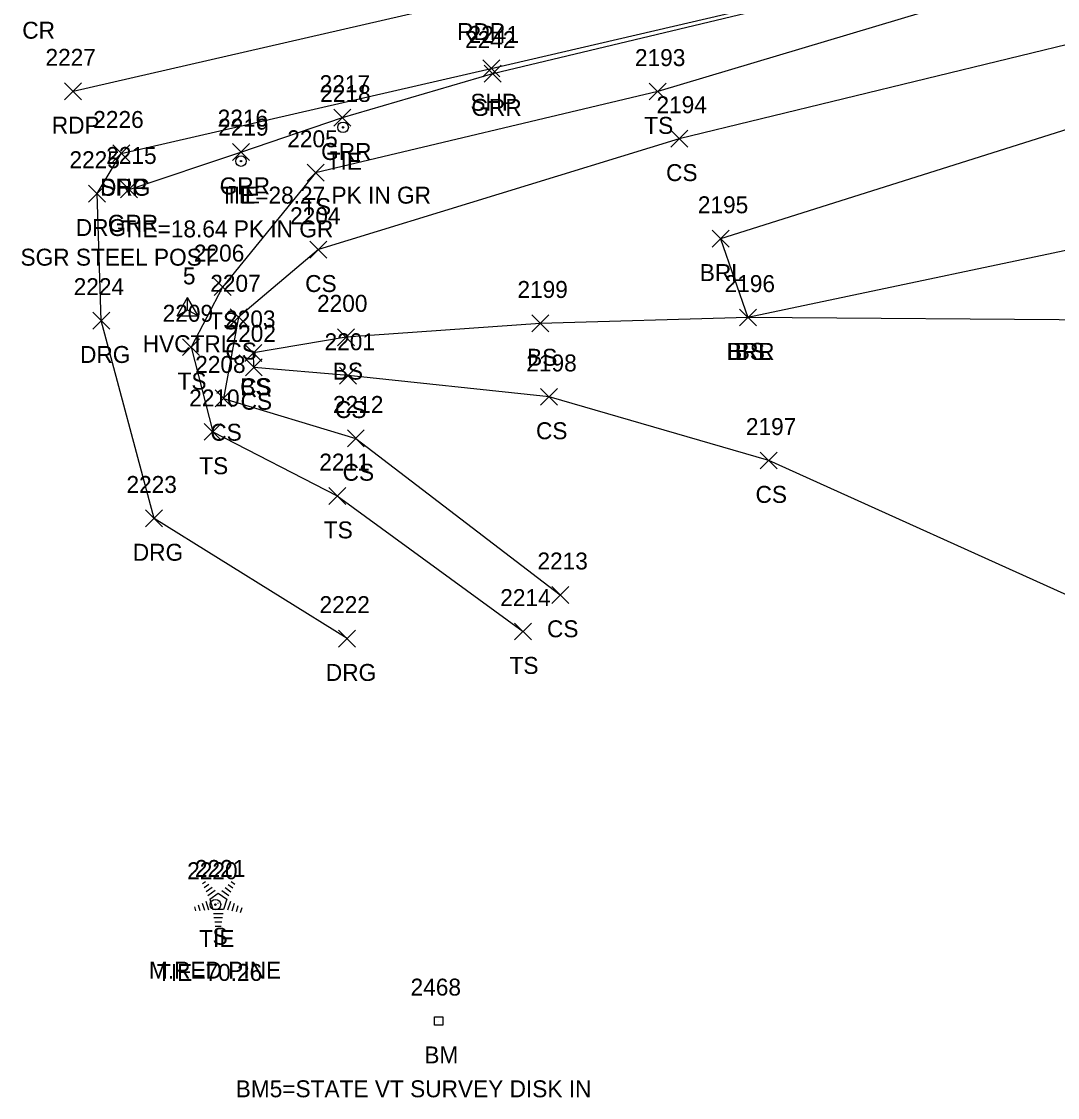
# Model space of a CAD drawing. Extents: x 1502194 to 1507887, y 142265 to 144150.
# Drawn here: x 1506530.8 to 1506653.1, y 143322.6 to 143449.6 of the extents above; entities that cross this region are included whole.
import ezdxf

# ---------------------------------------------------------------- set-up
doc = ezdxf.new("R2010")
doc.units = 0
for name, color, linetype in [('C_A', 7, 'Continuous'), ('C_C', 7, 'Continuous'), ('C_I', 7, 'Continuous'), ('CBP', 7, 'Continuous'), ('CPBM', 7, 'Continuous'), ('CPSM', 7, 'Continuous'), ('L_A', 7, 'Continuous'), ('L_C', 7, 'Continuous'), ('L_I', 7, 'Continuous'), ('L_TIC', 7, 'Continuous'), ('LABL', 7, 'Continuous'), ('LELB', 7, 'Continuous'), ('LTC', 7, 'Continuous'), ('P_A', 7, 'Continuous'), ('P_I', 7, 'Continuous'), ('P_TIC', 7, 'Continuous'), ('PET', 7, 'Continuous'), ('PSP', 7, 'Continuous'), ('R_A', 7, 'Continuous'), ('R_C', 7, 'Continuous'), ('R_I', 7, 'Continuous'), ('R_TIC', 7, 'Continuous'), ('RDG', 7, 'Continuous'), ('RGR', 7, 'Continuous')]:
    doc.layers.add(name, color=color, linetype=linetype)

msp = doc.modelspace()

# ---------------------------------------------------------------- linework, layer by layer
at = {"layer": 'CBP'}
for centre, radius in [((1506568.74, 143437.08), 0.625), ((1506568.74, 143437.08), 0.0833), ((1506556.7, 143433.1), 0.625), ((1506556.7, 143433.1), 0.0833), ((1506553.68, 143345.36), 0.625), ((1506553.68, 143345.36), 0.0833)]:
    msp.add_circle(centre, radius, dxfattribs=at)
at = {"layer": 'CPBM'}
for p, q in [((1506579.52, 143331.13), (1506579.52, 143332.13)), ((1506579.52, 143332.13), (1506580.52, 143332.13)), ((1506580.52, 143332.13), (1506580.52, 143331.13)), ((1506580.52, 143331.13), (1506579.52, 143331.13)), ((1506580.02, 143331.63), (1506580.02, 143331.63)), ((1506580.02, 143331.63), (1506580.02, 143331.63))]:
    msp.add_line(p, q, dxfattribs=at)
at = {"layer": 'CPSM'}
for p, q in [((1506549.15, 143414.83), (1506550.4, 143417)), ((1506551.65, 143414.83), (1506550.4, 143417)), ((1506550.4, 143415.55), (1506550.4, 143417)), ((1506549.15, 143414.83), (1506550.4, 143415.55)), ((1506549.15, 143414.83), (1506551.65, 143414.83)), ((1506550.4, 143415.55), (1506550.4, 143415.55)), ((1506550.4, 143415.55), (1506551.65, 143414.83))]:
    msp.add_line(p, q, dxfattribs=at)
at = {"layer": 'L_TIC'}
for points in [[(1506604.88, 143440.31), (1506606.88, 143442.31)], [(1506606.88, 143440.31), (1506604.88, 143442.31)], [(1506607.42, 143434.74), (1506609.42, 143436.74)], [(1506609.42, 143434.74), (1506607.42, 143436.74)], [(1506564.5, 143430.73), (1506566.5, 143432.73)], [(1506566.5, 143430.73), (1506564.5, 143432.73)], [(1506612.3, 143422.94), (1506614.3, 143424.94)], [(1506614.3, 143422.94), (1506612.3, 143424.94)], [(1506564.83, 143421.65), (1506566.83, 143423.65)], [(1506566.83, 143421.65), (1506564.83, 143423.65)], [(1506553.53, 143417.24), (1506555.53, 143419.24)], [(1506555.53, 143417.24), (1506553.53, 143419.24)], [(1506555.41, 143413.68), (1506557.41, 143415.68)], [(1506557.41, 143413.68), (1506555.41, 143415.68)], [(1506615.52, 143413.64), (1506617.52, 143415.64)], [(1506617.52, 143413.64), (1506615.52, 143415.64)], [(1506615.52, 143413.64), (1506617.52, 143415.64)], [(1506617.52, 143413.64), (1506615.52, 143415.64)], [(1506615.52, 143413.64), (1506617.52, 143415.64)], [(1506617.52, 143413.64), (1506615.52, 143415.64)], [(1506591.02, 143412.95), (1506593.02, 143414.95)], [(1506593.02, 143412.95), (1506591.02, 143414.95)], [(1506568.09, 143411.31), (1506570.09, 143413.31)], [(1506570.09, 143411.31), (1506568.09, 143413.31)], [(1506549.8, 143410.14), (1506551.8, 143412.14)], [(1506551.8, 143410.14), (1506549.8, 143412.14)], [(1506557.16, 143409.47), (1506559.16, 143411.47)], [(1506559.16, 143409.47), (1506557.16, 143411.47)], [(1506557.16, 143409.47), (1506559.16, 143411.47)], [(1506559.16, 143409.47), (1506557.16, 143411.47)], [(1506557.21, 143407.76), (1506559.21, 143409.76)], [(1506559.21, 143407.76), (1506557.21, 143409.76)], [(1506568.34, 143406.78), (1506570.34, 143408.78)], [(1506570.34, 143406.78), (1506568.34, 143408.78)], [(1506553.63, 143404.1), (1506555.63, 143406.1)], [(1506555.63, 143404.1), (1506553.63, 143406.1)], [(1506592.06, 143404.28), (1506594.06, 143406.28)], [(1506594.06, 143404.28), (1506592.06, 143406.28)], [(1506552.36, 143400.15), (1506554.36, 143402.15)], [(1506554.36, 143400.15), (1506552.36, 143402.15)], [(1506569.25, 143399.38), (1506571.25, 143401.38)], [(1506571.25, 143399.38), (1506569.25, 143401.38)], [(1506617.98, 143396.77), (1506619.98, 143398.77)], [(1506619.98, 143396.77), (1506617.98, 143398.77)], [(1506567.06, 143392.58), (1506569.06, 143394.58)], [(1506569.06, 143392.58), (1506567.06, 143394.58)], [(1506593.37, 143380.91), (1506595.37, 143382.91)], [(1506595.37, 143380.91), (1506593.37, 143382.91)], [(1506588.98, 143376.59), (1506590.98, 143378.59)], [(1506590.98, 143376.59), (1506588.98, 143378.59)]]:
    msp.add_lwpolyline(points, dxfattribs=at)
at = {"layer": 'LABL'}
for points in [[(1506925.15, 143533.52), (1506885.27, 143516.72), (1506839.01, 143491.82), (1506812.47, 143480.11), (1506797.79, 143478.92), (1506756.88, 143465.31), (1506714.98, 143450.06), (1506660.24, 143438.77), (1506613.3, 143423.94), (1506616.52, 143414.64)], [(1506850.82, 143464.05), (1506827.75, 143457.15), (1506806.24, 143448.63), (1506776.99, 143440.27), (1506769, 143436.63), (1506724.43, 143433.85), (1506664.3, 143424.7), (1506616.52, 143414.64)]]:
    msp.add_lwpolyline(points, dxfattribs=at)
at = {"layer": 'LELB'}
for points in [[(1506920.49, 143550.15), (1506879.81, 143532.73), (1506832.93, 143512.84), (1506791.89, 143498.35), (1506750.34, 143484.06), (1506703.75, 143467.85), (1506654.25, 143455.79), (1506605.88, 143441.31), (1506565.5, 143431.73), (1506554.53, 143418.24), (1506550.8, 143411.14), (1506553.36, 143401.15), (1506568.06, 143393.58), (1506589.98, 143377.59)], [(1506885.27, 143516.72), (1506836.36, 143503.21), (1506808.72, 143492.99), (1506794.07, 143487.49), (1506753.53, 143475.43), (1506709.32, 143458.78), (1506657.01, 143447.54), (1506608.42, 143435.74), (1506565.83, 143422.65), (1506556.41, 143414.68), (1506554.63, 143405.1), (1506570.25, 143400.38), (1506594.37, 143381.91)], [(1506682.41, 143418.03), (1506666.9, 143416.56), (1506658.47, 143414.34), (1506616.52, 143414.64), (1506592.02, 143413.95), (1506569.09, 143412.31), (1506558.16, 143410.47)], [(1506821.73, 143363.41), (1506805.08, 143357), (1506771.29, 143358.16), (1506752.16, 143369.48), (1506733.38, 143373.29), (1506711.32, 143372.85), (1506683.88, 143374.9), (1506657.49, 143380.4), (1506618.98, 143397.77), (1506593.06, 143405.28), (1506569.34, 143407.78), (1506558.21, 143408.76), (1506558.16, 143410.47)]]:
    msp.add_lwpolyline(points, dxfattribs=at)
at = {"layer": 'LTC'}
for p, q in [((1506552.15, 143347.84), (1506552.51, 143348.1)), ((1506552.36, 143347.37), (1506552.89, 143347.76)), ((1506552.57, 143346.91), (1506553.28, 143347.42)), ((1506552.78, 143346.44), (1506553.66, 143347.08)), ((1506554.44, 143347.03), (1506555.25, 143346.45)), ((1506554.81, 143347.38), (1506555.49, 143346.89)), ((1506555.18, 143347.73), (1506555.73, 143347.33)), ((1506555.55, 143348.08), (1506555.97, 143347.77)), ((1506552.55, 143345.77), (1506552.88, 143344.75)), ((1506553.01, 143345.99), (1506554.02, 143346.72)), ((1506553.01, 143345.99), (1506553.39, 143344.79)), ((1506554.02, 143346.72), (1506555.02, 143346)), ((1506555.02, 143346), (1506554.62, 143344.79)), ((1506551.19, 143345.12), (1506551.34, 143344.65)), ((1506551.64, 143345.33), (1506551.85, 143344.68)), ((1506552.1, 143345.55), (1506552.37, 143344.72)), ((1506554.62, 143344.79), (1506553.39, 143344.79)), ((1506555.45, 143345.73), (1506555.12, 143344.69)), ((1506555.9, 143345.48), (1506555.61, 143344.59)), ((1506556.34, 143345.23), (1506556.11, 143344.5)), ((1506556.79, 143344.97), (1506556.6, 143344.4)), ((1506554.59, 143344.29), (1506553.44, 143344.29)), ((1506554.5, 143343.79), (1506553.51, 143343.79)), ((1506554.42, 143343.29), (1506553.59, 143343.29)), ((1506554.34, 143342.79), (1506553.66, 143342.79))]:
    msp.add_line(p, q, dxfattribs=at)
at = {"layer": 'P_TIC'}
for points in [[(1506585.24, 143443.04), (1506587.24, 143445.04)], [(1506587.24, 143443.04), (1506585.24, 143445.04)], [(1506535.88, 143440.34), (1506537.88, 143442.34)], [(1506537.88, 143440.34), (1506535.88, 143442.34)], [(1506541.57, 143433.01), (1506543.57, 143435.01)], [(1506543.57, 143433.01), (1506541.57, 143435.01)]]:
    msp.add_lwpolyline(points, dxfattribs=at)
at = {"layer": 'PET'}
msp.add_lwpolyline([(1506536.88, 143441.34), (1506584.71, 143452.38), (1506632.33, 143463.25), (1506682.2, 143476.4), (1506730.21, 143490.72), (1506780.44, 143507.94), (1506828.66, 143525.9), (1506867.29, 143541.82), (1506915.31, 143562.43)], dxfattribs=at)
at = {"layer": 'PSP'}
msp.add_lwpolyline([(1506542.57, 143434.01), (1506586.24, 143444.04), (1506633.16, 143454.96), (1506684.08, 143468.88), (1506730.5, 143482.95), (1506782.84, 143500.58), (1506831.22, 143518.57), (1506871.13, 143534.59), (1506917.52, 143554.61)], dxfattribs=at)
at = {"layer": 'R_TIC'}
for points in [[(1506585.4, 143442.43), (1506587.4, 143444.43)], [(1506587.4, 143442.43), (1506585.4, 143444.43)], [(1506567.66, 143437.23), (1506569.66, 143439.23)], [(1506569.66, 143437.23), (1506567.66, 143439.23)], [(1506541.57, 143433.01), (1506543.57, 143435.01)], [(1506543.57, 143433.01), (1506541.57, 143435.01)], [(1506555.69, 143433.17), (1506557.69, 143435.17)], [(1506557.69, 143433.17), (1506555.69, 143435.17)], [(1506538.71, 143428.26), (1506540.71, 143430.26)], [(1506540.71, 143428.26), (1506538.71, 143430.26)], [(1506542.48, 143428.76), (1506544.48, 143430.76)], [(1506544.48, 143428.76), (1506542.48, 143430.76)], [(1506539.21, 143413.28), (1506541.21, 143415.28)], [(1506541.21, 143413.28), (1506539.21, 143415.28)], [(1506545.44, 143389.94), (1506547.44, 143391.94)], [(1506547.44, 143389.94), (1506545.44, 143391.94)], [(1506568.22, 143375.76), (1506570.22, 143377.76)], [(1506570.22, 143375.76), (1506568.22, 143377.76)]]:
    msp.add_lwpolyline(points, dxfattribs=at)
at = {"layer": 'RDG'}
msp.add_lwpolyline([(1506569.22, 143376.76), (1506546.44, 143390.94), (1506540.21, 143414.28), (1506539.71, 143429.26), (1506542.57, 143434.01)], dxfattribs=at)
at = {"layer": 'RGR'}
msp.add_lwpolyline([(1506543.48, 143429.76), (1506556.69, 143434.17), (1506568.66, 143438.23), (1506586.4, 143443.43), (1506633.04, 143454.6), (1506684.23, 143468.58), (1506730.71, 143482.6), (1506783.02, 143500.15), (1506831.56, 143518.03), (1506871.47, 143534.19), (1506917.7, 143554.27)], dxfattribs=at)

# ---------------------------------------------------------------- texts
at = {"layer": 'C_A'}
for s, p in [('TIE', (1506566.82, 143432.08)), ('TIE', (1506554.78, 143428.1)), ('HVCTRL', (1506545.1, 143410.55)), ('TIE', (1506551.76, 143340.36)), ('BM', (1506578.33, 143326.63))]:
    msp.add_text(s, height=2, dxfattribs=at).set_placement(p)
at = {"layer": 'C_C'}
for s, p in [('TIE=28.27 PK IN GR', (1506554.22, 143428.08)), ('TIE=18.64 PK IN GR', (1506542.69, 143424.1)), ('TIE=70.26', (1506546.78, 143336.36)), ('BM5=STATE VT SURVEY DISK IN', (1506556.07, 143322.63))]:
    msp.add_text(s, height=2, dxfattribs=at).set_placement(p)
at = {"layer": 'C_I'}
for s, p in [('2218', (1506566.05, 143440.08)), ('2219', (1506554, 143436.1)), ('5', (1506549.84, 143418.55)), ('2220', (1506550.34, 143348.36)), ('2468', (1506576.71, 143334.63))]:
    msp.add_text(s, height=2, dxfattribs=at).set_placement(p)
at = {"layer": 'L_A'}
for s, p in [('TS', (1506604.29, 143436.31)), ('CS', (1506606.86, 143430.74)), ('TS', (1506563.91, 143426.73)), ('BRL', (1506610.84, 143418.94)), ('CS', (1506564.27, 143417.65)), ('TS', (1506552.94, 143413.24)), ('CS', (1506554.85, 143409.68)), ('BS', (1506590.46, 143408.95)), ('BRR', (1506614.01, 143409.64)), ('BRL', (1506614.06, 143409.64)), ('BS', (1506614.96, 143409.64)), ('BS', (1506567.53, 143407.31)), ('TS', (1506549.21, 143406.14)), ('CS', (1506556.6, 143405.47)), ('BS', (1506556.6, 143405.47)), ('CS', (1506556.65, 143403.76)), ('CS', (1506567.78, 143402.78)), ('CS', (1506553.07, 143400.1)), ('CS', (1506591.51, 143400.28)), ('TS', (1506551.77, 143396.15)), ('CS', (1506568.69, 143395.38)), ('CS', (1506617.42, 143392.77)), ('TS', (1506566.47, 143388.58)), ('CS', (1506592.81, 143376.91)), ('TS', (1506588.39, 143372.59)), ('S', (1506553.34, 143340.63))]:
    msp.add_text(s, height=2, dxfattribs=at).set_placement(p)
at = {"layer": 'L_C'}
msp.add_text('M.RED PINE', height=2, dxfattribs=at).set_placement((1506545.83, 143336.63))
at = {"layer": 'L_I'}
for s, p in [('2193', (1506603.19, 143444.31)), ('2194', (1506605.73, 143438.74)), ('2205', (1506562.16, 143434.73)), ('2195', (1506610.61, 143426.94)), ('2204', (1506562.49, 143425.65)), ('2206', (1506551.14, 143421.24)), ('2207', (1506553.07, 143417.68)), ('2196', (1506613.77, 143417.64)), ('2196', (1506613.77, 143417.64)), ('2196', (1506613.77, 143417.64)), ('2199', (1506589.32, 143416.95)), ('2200', (1506565.67, 143415.31)), ('2209', (1506547.45, 143414.14)), ('2203', (1506554.82, 143413.47)), ('2203', (1506554.82, 143413.47)), ('2202', (1506554.87, 143411.76)), ('2201', (1506566.56, 143410.78)), ('2208', (1506551.29, 143408.1)), ('2198', (1506590.37, 143408.28)), ('2210', (1506550.58, 143404.15)), ('2212', (1506567.55, 143403.38)), ('2197', (1506616.28, 143400.77)), ('2211', (1506565.94, 143396.58)), ('2213', (1506591.68, 143384.91)), ('2214', (1506587.29, 143380.59)), ('2221', (1506551.27, 143348.63))]:
    msp.add_text(s, height=2, dxfattribs=at).set_placement(p)
at = {"layer": 'LTC'}
msp.add_text('.', height=1.04, rotation=270, dxfattribs=at).set_placement((1506553.9, 143345.73))
at = {"layer": 'P_A'}
for s, p in [('CR', (1506530.88, 143447.54)), ('RDP', (1506582.2, 143447.38)), ('SHP', (1506583.77, 143439.04)), ('RDP', (1506534.37, 143436.34)), ('SHP', (1506540.11, 143429.01))]:
    msp.add_text(s, height=2, dxfattribs=at).set_placement(p)
at = {"layer": 'P_I'}
for s, p in [('2241', (1506583.55, 143447.04)), ('2227', (1506533.62, 143444.34)), ('2226', (1506539.26, 143437.01))]:
    msp.add_text(s, height=2, dxfattribs=at).set_placement(p)
at = {"layer": 'R_A'}
for s, p in [('GRR', (1506583.88, 143438.43)), ('GRR', (1506566.15, 143433.23)), ('DRG', (1506540.06, 143429.01)), ('GRR', (1506554.18, 143429.17)), ('DRG', (1506537.2, 143424.26)), ('GRR', (1506540.97, 143424.76)), ('DRG', (1506537.7, 143409.28)), ('DRG', (1506543.93, 143385.94)), ('DRG', (1506566.71, 143371.76))]:
    msp.add_text(s, height=2, dxfattribs=at).set_placement(p)
at = {"layer": 'R_C'}
msp.add_text('SGR STEEL POST', height=2, dxfattribs=at).set_placement((1506530.67, 143420.76))
at = {"layer": 'R_I'}
for s, p in [('2242', (1506583.14, 143446.43)), ('2217', (1506565.97, 143441.23)), ('2226', (1506539.26, 143437.01)), ('2216', (1506553.94, 143437.17)), ('2215', (1506540.79, 143432.76)), ('2225', (1506536.45, 143432.26)), ('2224', (1506536.95, 143417.28)), ('2223', (1506543.18, 143393.94)), ('2222', (1506565.96, 143379.76))]:
    msp.add_text(s, height=2, dxfattribs=at).set_placement(p)

doc.saveas('drawing.dxf')
